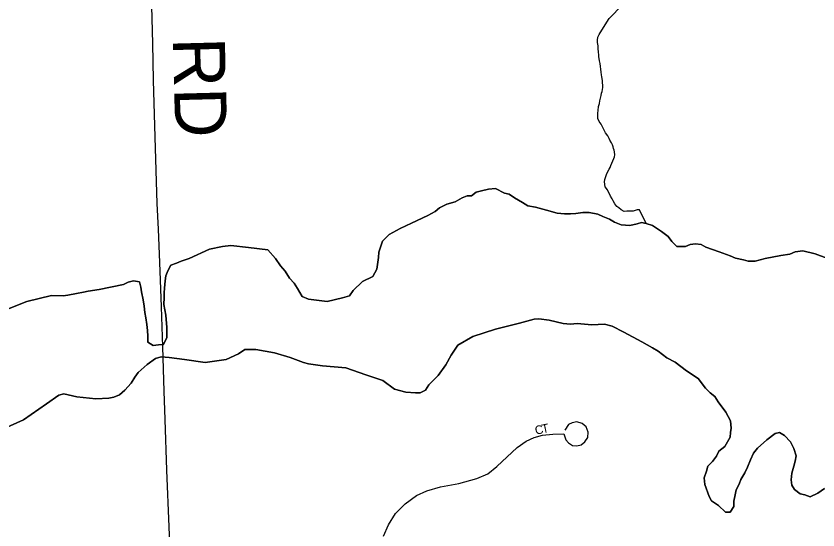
# Model space of a CAD drawing. Extents: x -10.1 to 68, y -9.5 to 29.2.
# Drawn here: x 3.483 to 4.36, y 18.175 to 18.737 of the extents above; entities that cross this region are included whole.
import ezdxf

# ---------------------------------------------------------------- set-up
doc = ezdxf.new("R2010")
doc.units = 0
for name, color, linetype in [('GM_X_County_Road', 7, 'Continuous'), ('GM_X_County_Road_Text', 7, 'Continuous'), ('GM_X_Major_Lake', 7, 'Continuous'), ('GM_X_Major_River', 7, 'Continuous'), ('GM_X_Minor_River', 7, 'Continuous'), ('GM_X_Township_Subdivision', 7, 'Continuous'), ('GM_X_Township_Subdivision_Text', 7, 'Continuous')]:
    doc.layers.add(name, color=color, linetype=linetype)

msp = doc.modelspace()

# ---------------------------------------------------------------- linework, layer by layer
at = {"layer": 'GM_X_County_Road'}
msp.add_lwpolyline([(3.63113, 18.76258), (3.63263, 18.7073), (3.63337, 18.66722), (3.63512, 18.60497), (3.63761, 18.53227), (3.63885, 18.50413), (3.64035, 18.46753), (3.64209, 18.41923), (3.64358, 18.37541), (3.64508, 18.32686), (3.64632, 18.29599), (3.64806, 18.24046), (3.65055, 18.17847), (3.6523, 18.13266)], dxfattribs=at)
at = {"layer": 'GM_X_Major_Lake'}
for points in [[(4.01756, 18.5436), (4.00765, 18.54879), (4.00009, 18.54793), (3.99253, 18.54594), (3.98649, 18.54472), (3.98161, 18.54048), (3.97668, 18.54079), (3.9714, 18.53845), (3.9635, 18.53417), (3.95444, 18.53139), (3.94653, 18.52749), (3.94165, 18.52363), (3.93375, 18.51897), (3.91604, 18.51076), (3.90361, 18.5049), (3.89156, 18.49829), (3.88407, 18.49097), (3.88004, 18.47914), (3.87974, 18.47306), (3.87799, 18.46049), (3.87354, 18.45245), (3.86224, 18.44699), (3.85213, 18.43698), (3.84803, 18.43123), (3.84048, 18.42885), (3.82386, 18.42484), (3.80336, 18.42762), (3.79651, 18.43057), (3.7911, 18.43924), (3.78763, 18.4449), (3.78264, 18.45054), (3.77762, 18.45807), (3.77263, 18.46409), (3.76723, 18.472), (3.75878, 18.4814), (3.73754, 18.48416), (3.71819, 18.4862), (3.70911, 18.48532), (3.69513, 18.4821), (3.6729, 18.47194), (3.66422, 18.46917), (3.65894, 18.46682), (3.6529, 18.46485), (3.64956, 18.45872), (3.64736, 18.45299), (3.64666, 18.44766), (3.646, 18.43968), (3.64531, 18.43435), (3.64537, 18.42941), (3.64507, 18.4218), (3.64711, 18.41005), (3.64841, 18.39638), (3.64853, 18.38574), (3.64483, 18.3781), (3.63916, 18.37764), (3.63348, 18.37681), (3.62775, 18.38054), (3.62768, 18.387), (3.62722, 18.39345), (3.62639, 18.3999), (3.62555, 18.40711), (3.62434, 18.4128), (3.6235, 18.42001), (3.62266, 18.42684), (3.62067, 18.43555), (3.61985, 18.44086), (3.61864, 18.44655), (3.61181, 18.4476), (3.60615, 18.44601), (3.60087, 18.44366), (3.57442, 18.438), (3.56231, 18.43633), (3.5574, 18.43513), (3.54946, 18.43388), (3.54002, 18.43186), (3.5351, 18.43104), (3.52221, 18.43164), (3.49539, 18.42483), (3.47428, 18.41659)], [(4.36997, 18.47246), (4.35742, 18.47724), (4.34374, 18.48048), (4.33542, 18.47924), (4.32976, 18.47689), (4.31993, 18.47524), (4.30254, 18.47198), (4.29159, 18.46918), (4.28401, 18.46908), (4.27907, 18.47054), (4.27034, 18.47233), (4.26425, 18.47491), (4.25245, 18.47932), (4.23762, 18.48445), (4.23265, 18.48743), (4.22658, 18.48811), (4.22053, 18.48728), (4.21563, 18.48532), (4.20616, 18.48519), (4.20041, 18.49082), (4.19656, 18.49609), (4.1893, 18.5017), (4.17937, 18.50804), (4.17253, 18.51023), (4.16759, 18.5113), (4.16268, 18.5101), (4.15475, 18.5081), (4.14527, 18.50874), (4.13803, 18.51169), (4.13231, 18.51504), (4.12508, 18.51798), (4.11975, 18.52058), (4.11025, 18.52236), (4.10343, 18.52227), (4.09549, 18.52141), (4.08981, 18.52095), (4.08337, 18.52087), (4.07503, 18.52153), (4.06363, 18.5248), (4.05146, 18.52807), (4.04311, 18.52986), (4.03739, 18.53321), (4.02861, 18.53842), (4.02288, 18.54252), (4.01756, 18.5436)], [(3.45807, 18.28071), (3.49161, 18.29558), (3.51679, 18.313), (3.53031, 18.32267), (3.5356, 18.32388), (3.55004, 18.32064), (3.5709, 18.31863), (3.58491, 18.31919), (3.59058, 18.3204), (3.59661, 18.32276), (3.60261, 18.32815), (3.60935, 18.33546), (3.61343, 18.34235), (3.61716, 18.34734), (3.62691, 18.35621), (3.63592, 18.36278), (3.64234, 18.36438), (3.65106, 18.36373), (3.66776, 18.36167), (3.69015, 18.35815), (3.71322, 18.36148), (3.72679, 18.36774), (3.73355, 18.37238), (3.74567, 18.37254), (3.76617, 18.369), (3.78328, 18.3639), (3.79774, 18.35838), (3.80344, 18.35693), (3.81862, 18.35447), (3.84403, 18.35251), (3.86609, 18.34481), (3.88473, 18.33859), (3.89734, 18.32925), (3.90989, 18.32561), (3.92012, 18.32498), (3.92543, 18.32504), (3.93107, 18.32816), (3.93479, 18.33391), (3.9449, 18.34391), (3.95348, 18.3558), (3.95942, 18.36614), (3.96649, 18.37725), (3.98304, 18.38658), (4.00795, 18.39488), (4.03402, 18.40129), (4.04988, 18.40568), (4.05517, 18.40612), (4.06656, 18.40475), (4.08176, 18.40076), (4.08972, 18.4001), (4.09691, 18.40096), (4.11321, 18.39964), (4.12685, 18.4002), (4.13521, 18.39802), (4.14817, 18.39135), (4.16761, 18.38095), (4.17943, 18.37426), (4.18554, 18.37054), (4.19509, 18.36344), (4.20424, 18.35862), (4.21648, 18.34927), (4.22946, 18.3407), (4.23754, 18.33016), (4.24252, 18.3249), (4.24749, 18.32117), (4.25135, 18.31514), (4.25982, 18.30384), (4.26486, 18.29441), (4.26533, 18.28643), (4.26463, 18.28148), (4.26431, 18.27654), (4.26134, 18.27156), (4.25837, 18.2662), (4.25199, 18.26118), (4.2494, 18.25583), (4.24492, 18.25007), (4.24006, 18.24469), (4.23861, 18.23935), (4.23604, 18.23209), (4.2365, 18.22488), (4.24159, 18.21164), (4.24392, 18.20673), (4.25155, 18.20189), (4.25922, 18.19438), (4.26452, 18.19445), (4.26824, 18.20058), (4.26854, 18.20666), (4.26998, 18.21352), (4.27105, 18.21886), (4.27439, 18.22498)], [(4.27439, 18.22498), (4.27622, 18.23032), (4.2803, 18.2376), (4.28326, 18.24372), (4.28658, 18.25174), (4.2899, 18.259), (4.29438, 18.26438), (4.3045, 18.27363), (4.31351, 18.28058), (4.31842, 18.28179), (4.32377, 18.27843), (4.33029, 18.2713), (4.33417, 18.26412), (4.33653, 18.25618), (4.33546, 18.25046), (4.33402, 18.24474), (4.33183, 18.23711), (4.33116, 18.22988), (4.33198, 18.22419), (4.33469, 18.21929), (4.34081, 18.21443), (4.34613, 18.21335), (4.35184, 18.21115), (4.36012, 18.21543), (4.36764, 18.22047)]]:
    msp.add_lwpolyline(points, dxfattribs=at)
at = {"layer": 'GM_X_Major_River'}
for points in [[(3.47428, 18.41659), (3.49539, 18.42483), (3.52221, 18.43164), (3.5351, 18.43104), (3.54002, 18.43186), (3.54946, 18.43388), (3.5574, 18.43513), (3.56231, 18.43633), (3.57442, 18.438), (3.60087, 18.44366), (3.60615, 18.44601), (3.61181, 18.4476), (3.61864, 18.44655), (3.61985, 18.44086), (3.62067, 18.43555), (3.62266, 18.42684), (3.6235, 18.42001), (3.62434, 18.4128), (3.62555, 18.40711), (3.62639, 18.3999), (3.62722, 18.39345), (3.62768, 18.387), (3.62775, 18.38054), (3.63348, 18.37681), (3.63916, 18.37764), (3.64483, 18.3781), (3.64853, 18.38574), (3.64841, 18.39638), (3.64711, 18.41005), (3.64507, 18.4218), (3.64537, 18.42941), (3.64531, 18.43435), (3.646, 18.43968), (3.64666, 18.44766), (3.64736, 18.45299), (3.64956, 18.45872), (3.6529, 18.46485), (3.65894, 18.46682), (3.66422, 18.46917), (3.6729, 18.47194), (3.69513, 18.4821), (3.70911, 18.48532), (3.71819, 18.4862), (3.73754, 18.48416), (3.75878, 18.4814), (3.76723, 18.472), (3.77263, 18.46409), (3.77762, 18.45807), (3.78264, 18.45054), (3.78763, 18.4449), (3.7911, 18.43924), (3.79651, 18.43057), (3.80336, 18.42762), (3.82386, 18.42484), (3.84048, 18.42885), (3.84803, 18.43123), (3.85213, 18.43698), (3.86224, 18.44699), (3.87354, 18.45245), (3.87799, 18.46049), (3.87974, 18.47306), (3.88004, 18.47914), (3.88407, 18.49097), (3.89156, 18.49829), (3.90361, 18.5049), (3.91604, 18.51076), (3.93375, 18.51897), (3.94165, 18.52363), (3.94653, 18.52749), (3.95444, 18.53139), (3.9635, 18.53417), (3.9714, 18.53845), (3.97668, 18.54079), (3.98161, 18.54048), (3.98649, 18.54472), (3.99253, 18.54594), (4.00009, 18.54793), (4.00765, 18.54879), (4.01756, 18.5436)], [(4.01756, 18.5436), (4.02288, 18.54252), (4.02861, 18.53842), (4.03739, 18.53321), (4.04311, 18.52986), (4.05146, 18.52807), (4.06363, 18.5248), (4.07503, 18.52153), (4.08337, 18.52087), (4.08981, 18.52095), (4.09549, 18.52141), (4.10343, 18.52227), (4.11025, 18.52236), (4.11975, 18.52058), (4.12508, 18.51798), (4.13231, 18.51504), (4.13803, 18.51169), (4.14527, 18.50874), (4.15475, 18.5081), (4.16268, 18.5101), (4.16759, 18.5113), (4.17253, 18.51023), (4.17937, 18.50804), (4.1893, 18.5017), (4.19656, 18.49609), (4.20041, 18.49082), (4.20616, 18.48519), (4.21563, 18.48532), (4.22053, 18.48728), (4.22658, 18.48811), (4.23265, 18.48743), (4.23762, 18.48445), (4.25245, 18.47932), (4.26425, 18.47491), (4.27034, 18.47233), (4.27907, 18.47054), (4.28401, 18.46908), (4.29159, 18.46918), (4.30254, 18.47198), (4.31993, 18.47524), (4.32976, 18.47689), (4.33542, 18.47924), (4.34374, 18.48048), (4.35742, 18.47724), (4.36997, 18.47246)], [(4.27439, 18.22498), (4.27105, 18.21886), (4.26998, 18.21352), (4.26854, 18.20666), (4.26824, 18.20058), (4.26452, 18.19445), (4.25922, 18.19438), (4.25155, 18.20189), (4.24392, 18.20673), (4.24159, 18.21164), (4.2365, 18.22488), (4.23604, 18.23209), (4.23861, 18.23935), (4.24006, 18.24469), (4.24492, 18.25007), (4.2494, 18.25583), (4.25199, 18.26118), (4.25837, 18.2662), (4.26134, 18.27156), (4.26431, 18.27654), (4.26463, 18.28148), (4.26533, 18.28643), (4.26486, 18.29441), (4.25982, 18.30384), (4.25135, 18.31514), (4.24749, 18.32117), (4.24252, 18.3249), (4.23754, 18.33016), (4.22946, 18.3407), (4.21648, 18.34927), (4.20424, 18.35862), (4.19509, 18.36344), (4.18554, 18.37054), (4.17943, 18.37426), (4.16761, 18.38095), (4.14817, 18.39135), (4.13521, 18.39802), (4.12685, 18.4002), (4.11321, 18.39964), (4.09691, 18.40096), (4.08972, 18.4001), (4.08176, 18.40076), (4.06656, 18.40475), (4.05517, 18.40612), (4.04988, 18.40568), (4.03402, 18.40129), (4.00795, 18.39488), (3.98304, 18.38658), (3.96649, 18.37725), (3.95942, 18.36614), (3.95348, 18.3558), (3.9449, 18.34391), (3.93479, 18.33391), (3.93107, 18.32816), (3.92543, 18.32504), (3.92012, 18.32498), (3.90989, 18.32561), (3.89734, 18.32925), (3.88473, 18.33859), (3.86609, 18.34481), (3.84403, 18.35251), (3.81862, 18.35447), (3.80344, 18.35693), (3.79774, 18.35838), (3.78328, 18.3639), (3.76617, 18.369), (3.74567, 18.37254), (3.73355, 18.37238), (3.72679, 18.36774), (3.71322, 18.36148), (3.69015, 18.35815), (3.66776, 18.36167), (3.65106, 18.36373), (3.64234, 18.36438), (3.63592, 18.36278), (3.62691, 18.35621), (3.61716, 18.34734), (3.61343, 18.34235), (3.60935, 18.33546), (3.60261, 18.32815), (3.59661, 18.32276), (3.59058, 18.3204), (3.58491, 18.31919), (3.5709, 18.31863), (3.55004, 18.32064), (3.5356, 18.32388), (3.53031, 18.32267), (3.51679, 18.313), (3.49161, 18.29558), (3.45807, 18.28071)], [(4.36764, 18.22047), (4.36012, 18.21543), (4.35184, 18.21115), (4.34613, 18.21335), (4.34081, 18.21443), (4.33469, 18.21929), (4.33198, 18.22419), (4.33116, 18.22988), (4.33183, 18.23711), (4.33402, 18.24474), (4.33546, 18.25046), (4.33653, 18.25618), (4.33417, 18.26412), (4.33029, 18.2713), (4.32377, 18.27843), (4.31842, 18.28179), (4.31351, 18.28058), (4.3045, 18.27363), (4.29438, 18.26438), (4.2899, 18.259), (4.28658, 18.25174), (4.28326, 18.24372), (4.2803, 18.2376), (4.27622, 18.23032), (4.27439, 18.22498)]]:
    msp.add_lwpolyline(points, dxfattribs=at)
at = {"layer": 'GM_X_Minor_River'}
for points in [[(4.14662, 18.74967), (4.13224, 18.73456)], [(4.17253, 18.51023), (4.16535, 18.52533), (4.16269, 18.52527), (4.16042, 18.52445), (4.15815, 18.52402), (4.15473, 18.52394), (4.1513, 18.52386), (4.14865, 18.52342), (4.14518, 18.52525), (4.14247, 18.52747), (4.14053, 18.52895), (4.13818, 18.53194), (4.13658, 18.53533), (4.1354, 18.5372), (4.13343, 18.5402), (4.13262, 18.54208), (4.13142, 18.54472), (4.13022, 18.54736), (4.12787, 18.55035), (4.12698, 18.55604), (4.12731, 18.55833), (4.12801, 18.56063), (4.12908, 18.56408), (4.13016, 18.56638), (4.13199, 18.56985), (4.13308, 18.57178), (4.1338, 18.57369), (4.13488, 18.57638), (4.13596, 18.57907), (4.13705, 18.58138), (4.13777, 18.5833), (4.1381, 18.58559), (4.13803, 18.58863), (4.1376, 18.59052), (4.1368, 18.59241), (4.13637, 18.5943), (4.13556, 18.59657), (4.13476, 18.59845), (4.13279, 18.60145), (4.13198, 18.60333), (4.13077, 18.60635), (4.12803, 18.60971), (4.12645, 18.61234), (4.12524, 18.61536), (4.12325, 18.61911), (4.12128, 18.62211), (4.11969, 18.62512), (4.1196, 18.62893), (4.11955, 18.63121), (4.11987, 18.63388), (4.12052, 18.63846), (4.1216, 18.64153), (4.12191, 18.64458), (4.1226, 18.64764), (4.1233, 18.65032), (4.12362, 18.65299), (4.12433, 18.65491), (4.12467, 18.65682), (4.125, 18.65911), (4.12482, 18.66672), (4.12397, 18.67088), (4.12353, 18.67316), (4.12347, 18.67582), (4.12302, 18.67923), (4.12256, 18.68227), (4.12211, 18.6853), (4.12167, 18.68833), (4.12122, 18.69099), (4.1208, 18.69288), (4.12076, 18.69478), (4.12031, 18.69782), (4.12021, 18.702), (4.12015, 18.70466), (4.11973, 18.70656), (4.1193, 18.70845), (4.11924, 18.71111), (4.11955, 18.71416), (4.121, 18.71724), (4.1221, 18.71917), (4.13224, 18.73456)]]:
    msp.add_lwpolyline(points, dxfattribs=at)
at = {"layer": 'GM_X_Township_Subdivision'}
msp.add_lwpolyline([(3.88534, 18.16826), (3.89082, 18.18071), (3.89854, 18.19291), (3.909, 18.20361), (3.92144, 18.21258), (3.93265, 18.21781), (3.94759, 18.22204), (3.96751, 18.22577), (3.98742, 18.2315), (3.99938, 18.23648), (4.00933, 18.24445), (4.03149, 18.26511), (4.04145, 18.27233), (4.05017, 18.27632), (4.05913, 18.27856), (4.07058, 18.2798), (4.08253, 18.28005), (4.08453, 18.27358), (4.08751, 18.27034), (4.092, 18.26735), (4.09673, 18.2671), (4.10146, 18.2681), (4.10544, 18.27159), (4.10868, 18.27607), (4.10893, 18.28204), (4.10693, 18.28777), (4.1027, 18.2915), (4.09673, 18.29325), (4.0915, 18.29225), (4.08751, 18.29051), (4.08353, 18.28404)], dxfattribs=at)

# ---------------------------------------------------------------- texts
at = {"layer": 'GM_X_County_Road_Text'}
msp.add_text('RD', height=0.056818, rotation=271.4703, dxfattribs=at).set_placement((3.65491, 18.71343))
at = {"layer": 'GM_X_Township_Subdivision_Text'}
for s, rotation, p in [('C', 13.42962, (4.05209, 18.27903)), ('T', 11.66354, (4.05931, 18.28076))]:
    msp.add_text(s, height=0.00947, rotation=rotation, dxfattribs=at).set_placement(p)

doc.saveas('drawing.dxf')
